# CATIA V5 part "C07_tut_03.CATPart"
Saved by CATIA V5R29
Part number: Part1
Bounding box of the stored display mesh (mm): x 0 to 108, y -52.5 to 52.5, z -52.5 to 52.5
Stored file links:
  C:\Users\CADCIM 00\Desktop\catia parts file\c07\C07_tut_03.CATPart
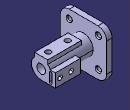
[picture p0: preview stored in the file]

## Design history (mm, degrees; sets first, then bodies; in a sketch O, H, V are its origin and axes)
Body1 (main body)
  Sketch1 on yz-plane, origin (0, 0, 0), H (0, 1, 0), V (0, 0, 1)
    line L1 (52.5, 32.5) -> (52.5, -32.5)
    line L2 (32.5, -52.5) -> (-32.5, -52.5)
    line L3 (-52.5, -32.5) -> (-52.5, 32.5)
    line L4 (-32.5, 52.5) -> (32.5, 52.5)
    point P1 (52.5, 52.5)
    point P2 (52.5, -52.5)
    point P3 (-52.5, -52.5)
    arc A1 centre (32.5, 32.5) radius 20 from (52.5, 32.5) to (32.5, 52.5) ccw
    arc A2 centre (32.5, -32.5) radius 20 from (52.5, -32.5) to (32.5, -52.5) cw
    arc A3 centre (-32.5, -32.5) radius 20 from (-32.5, -52.5) to (-52.5, -32.5) cw
    arc A4 centre (-32.5, 32.5) radius 20 from (-52.5, 32.5) to (-32.5, 52.5) cw
    distance P1 P2 = 105
    radius A1 = 20
    distance P2 P3 = 105
    radius A2 = 20
    radius A3 = 20
    radius A4 = 20
    vertical: L1 V, L3 V
    horizontal: L2 H, L4 H
    equidistance: L1 L3 O, L2 L4 O
    coincidence: L1 P1, L4 P1, L1 P2, L2 P2, L2 P3, L3 P3
    tangency: A1 L1, A1 L4, A2 L1, A2 L2, A3 L2, A3 L3, A4 L3, A4 L4
  Pad1: profile Sketch1, direction (1, 0, 0), length 12
  Sketch2 on face of Pad1, origin (12, 0, 0), H (0, 1, 0), V (0, 0, 1)
    circle A1 centre (0, 0) radius 22
    radius A1 = 22
  Pad2: profile Sketch2, direction (1, 0, 0), length 96
  Sketch3 on face of Pad2, origin (108, 0, 0), H (0, 1, 0), V (0, 0, 1)
    point P1 (-15, 16.0935)
    line L1 (-15, 16.0935) -> (-15, 25)
    line L2 (-15, 25) -> (15, 25)
    line L3 (15, 25) -> (15, 16.0935)
    point P4 (15, 16.0935)
    axis line L4 (0, 0) -> (0, 25)
    point P5 (0, 25)
    reference projected circle E1 centre (0, 0) radius 22 from edge [face of Pad2 | face of Pad2]
    reference projected circle E2 centre (0, 0) radius 22 from edge [face of Pad2 | face of Pad2]
    projected circle E3 centre (0, 0) radius 22 from edge [face of Pad2 | face of Pad2]
    projected arc E4 centre (0, 0) radius 22 from (15, 16.0935) to (-15, 16.0935) ccw from edge [face of Pad2 | face of Pad2]
    length L2 = 30
    distance H L2 = 25
    vertical: L1 V, L3 V, L4 V
    horizontal: L2 H
    midpoint: P5 L2
    coincidence: P4 E1, P1 E2
  Pad3: profile Sketch3, direction (-1, 0, 0), length 76
  Sketch4 on face of Pad2, origin (108, 0, 0), H (0, 1, 0), V (0, 0, 1)
    point P1 (0, -22)
    line L1 (0, -22) -> (32, -22)
    line L2 (32, -22) -> (32, 8)
    line L3 (32, 8) -> (20.4939, 8)
    point P4 (20.4939, 8)
    reference projected circle E1 centre (0, 0) radius 22 from edge of Pad2
    reference projected circle E2 centre (0, 0) radius 22 from edge [face of Pad2 | face of Pad2]
    reference projected circle E3 centre (0, 0) radius 22 from edge [face of Pad2 | face of Pad2]
    projected arc E4 centre (0, 0) radius 22 from (-15, 16.0935) to (15, 16.0935) ccw from edge of Pad3
    projected arc E5 centre (0, 0) radius 22 from (0, -22) to (20.4939, 8) ccw from edge of Pad3
    length L2 = 30
    distance V L2 = 32
    coincidence: P1 V, P4 E1, P1 E2
    horizontal: L1 H, L3 H
    vertical: L2 V
    tangency: L1 E3
  Pad4: profile Sketch4, direction (-1, 0, 0), length 57
  Sketch5 on face of Pad2, origin (108, 0, 0), H (0, 1, 0), V (0, 0, 1)
    line L1 (24.5, 2.5) -> (24.5, -16.5)
    line L2 (18.5, -16.5) -> (18.5, 2.5)
    point P4 (18.5, -16.5)
    arc A1 centre (21.5, 2.5) radius 3 from (24.5, 2.5) to (18.5, 2.5) ccw
    point P5 (21.5, 2.5)
    arc A2 centre (21.5, -16.5) radius 3 from (18.5, -16.5) to (24.5, -16.5) ccw
    point P6 (21.5, -16.5)
    point P7 (18.5, -16.5)
    reference projected line E1 (52.5, -32.5) -> (52.5, 32.5) from edge [face of Pad1 from Sketch1.L1 | end face of Pad1]
    reference projected line E2 (-32.5, -52.5) -> (32.5, -52.5) from edge [face of Pad1 from Sketch1.L2 | end face of Pad1]
    length L1 = 19
    distance L1 P5 = 3
    distance L2 E1 = 34
    distance P6 E2 = 36
    vertical: L1 V, L2 V
    tangency: A1 L1, A2 L1, A2 L2, A1 L2
    coincidence: P4 P7
  Pocket1: profile Sketch5, direction (-1, 0, 0), length 50
  Sketch6 on face of Pad2, origin (108, 0, 0), H (0, 1, 0), V (0, 0, 1)
    point P1 (0, 0)
    coincidence: P1 O
  Hole1: placed by Sketch6, at (108, 0, 0) direction (-1, 0, 0), diameter 20, up to end face of Pad1
  Sketch7 on face of Pad3, origin (90.7325, -5.9449, 25), H (1, 0, 0), V (0, 1, 0)
    point P1 (1.2675, 5.9449)
    reference projected line E1 (17.2675, -9.0551) -> (-58.7325, -9.0551) from edge [face of Pad3 | face of Pad3]
    reference projected line E2 (17.2675, 20.9449) -> (17.2675, -9.0551) from edge [face of Pad3 | face of Pad3]
    distance P1 E1 = 15
    distance P1 E2 = 16
  Hole2: placed by Sketch7, at (92, 0, 25) direction (0, 0, -1), diameter 12, depth 33.0037, threaded, thread diameter 13.2, thread depth 10, pitch 1
  RectPattern1: of Hole2, direction 1 instances 2, spacing 44, along edge [face of Pad3 | face of Pad3]
  Sketch8 on face of Pad4, origin (86.2721, 32, -2.7131), H (1, 0, 0), V (0, 0, -1)
    point P1 (10.7279, 4.2869)
    reference projected line E1 (21.7279, 19.2869) -> (-35.2721, 19.2869) from edge [face of Pad4 | face of Pad4]
    reference projected line E2 (21.7279, 19.2869) -> (21.7279, -10.7131) from edge [face of Pad4 | face of Pad4]
    distance P1 E1 = 15
    distance E2 P1 = 11
  Hole3: placed by Sketch8, at (97, 32, -7) direction (0, -1, 0), diameter 10, through (limit type 6)
  RectPattern2: of Hole3, direction 1 instances 2, spacing 25, along edge [face of Pad4 | face of Pad4], direction 2 instances 2, spacing 76
  Sketch9 on face of Pad1, origin (12, -36.1764, 22.8739), H (0, 1, 0), V (0, 0, 1)
    point P1 (3.6764, -55.3739)
    reference projected line E1 (-16.3236, 9.6261) -> (-16.3236, -55.3739) from edge [face of Pad1 | face of Pad1]
    reference projected line E2 (3.6764, -75.3739) -> (68.6764, -75.3739) from edge [face of Pad1 | face of Pad1]
    distance P1 E1 = 20
    distance E2 P1 = 20
  Hole4: placed by Sketch9, at (12, -32.5, -32.5) direction (-1, 0, 0), diameter 10, through (limit type 3), countersink depth 2, countersink angle 90
  RectPattern3: of Hole4, direction 1 instances 2, spacing 66, along edge [face of Pad1 | face of Pad1], direction 2 instances 2, spacing 66, along edge [face of Pad1 | face of Pad1] reversed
